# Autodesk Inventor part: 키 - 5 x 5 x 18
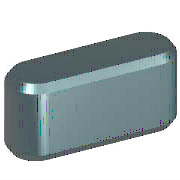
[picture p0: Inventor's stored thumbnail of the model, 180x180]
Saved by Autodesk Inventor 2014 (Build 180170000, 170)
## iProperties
Created: 2012-02
Part Number: 키 - 5 x 5 x 18
Material: 강철, 연강
Description: 키 및 해당 키홈
Document SubType Name: Modeling
Standard: KS B 1311
Designer: mduedu
Standards Organization: KS
Language: ko-KR
Size Designation: 5 x 5 x 18
Categories: <MemberInstance><Categories><Category DisplayName="샤프트 부품" InternalName="7f7aeb1f-a693-4053-b835-cee3144e0d98" Mnemonic="SHFT"><Category DisplayName="키" Interna
Density: 7.86 g/cm^3
Mass: 3.27476 g
Surface Area: 3.57848 cm^2
Volume: 0.416636 cm^3
Appearance: Yellow
IsCustomPart: 1
Author: mduedu
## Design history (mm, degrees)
sketch "스케치1"
  geometry: L1 (2.5, 2.5)-(15.5, 2.5); L2 (15.5, -2.5)-(2.5, -2.5); L3 (0, 9.4)-(0, -7.4) reference; L4 (-5, 0)-(30, 0) reference; L5 (18, 0)-(18, 7); A1 r 2.5 centre (2.5, 0) between (2.5, 2.5) and (2.5, -2.5); A2 r 2.5 centre (15.5, 0) between (15.5, -2.5) and (15.5, 2.5)
  constraints: 6 end point, 5 point on circle, 4 tangent, 3 point on line, 2 centre point, 1 horizontal, 1 parallel, 1 perpendicular
  dimensions: "d0" = 2.5 radius of A1 (= 0.5 x PB); "d13" = 2.5 radius of A2 (= 0.5 x PB); "d14" = 18 distance between parallel lines of L5 L3 (= NLG)
extrude "본체1" new body sketch "스케치1" taper "d3" = 0 deg; stored distance "d4" = 10
workplane "Work Plane3"
body "Solid1"
workplane "Work Plane1"
workplane "Work Plane2"
chamfer "모따기1" distance "d8" = 0.4 (= PHH); stored, may be unused: second distance "d9" = 0.4 (= PHH), angle "d15" = 45 deg
other parameters: "d1" = -3 (= -PNT), "d2" = 2 (= PH - PNT), "NLG" = 18 [user parameter; used in 3 equation terms], "PB" = 5 [user parameter; used in 2 equation terms], "PNT" = 3 [user parameter; used in 2 equation terms], "PH" = 5 [user parameter; used in 1 equation term], "PHH" = 0.4 [user parameter; used in 2 equation terms], "d10" = 0, "d16" = 0, "d17" = 0, "d18" = 0, "WDMIN" = 12 [user parameter], "PLB2" = 18 (= NLG) [user parameter], "WDMAX" = 17 [user parameter], "PLB1" = 18 (= NLG) [user parameter], "RR" = 0.16 [user parameter], "PUEB" = 2.3 [user parameter]
